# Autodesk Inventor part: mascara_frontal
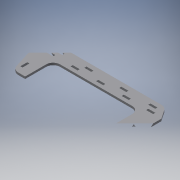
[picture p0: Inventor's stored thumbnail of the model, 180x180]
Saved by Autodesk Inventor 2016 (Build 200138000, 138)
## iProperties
Created: 2017-06
Part Number: mascara_frontal
Material: Generic
Document SubType Name: Modeling
Designer: laboratorioesan
Density: 1 g/cm^3
Appearance: Default
Author: laboratorioesan
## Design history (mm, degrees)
sketch "Sketch1"
  geometry: L1 (280, 0)-(340, 0) reference; L2 (340, 0)-(340, 18.5) reference; L3 (280, 18.5)-(340, 18.5) reference; L4 (280, 0)-(280, 18.5) reference; L5 (70, 0)-(130, 0) reference; L6 (130, 0)-(130, 18.5) reference; L7 (70, 18.5)-(130, 18.5) reference; L8 (70, 0)-(70, 18.5) reference; L9 (500, 0)-(560, 0) reference; L10 (560, 0)-(560, 18.5) reference; L11 (500, 18.5)-(560, 18.5) reference; L12 (500, 0)-(500, 18.5) reference; L13 (720, 0)-(780, 0) reference; L14 (780, 0)-(780, 18.5) reference; L15 (720, 18.5)-(780, 18.5) reference; L16 (720, 0)-(720, 18.5) reference; L17 (930, 0)-(990, 0) reference; L18 (990, 0)-(990, 18.5) reference; L19 (930, 18.5)-(990, 18.5) reference; L20 (930, 0)-(930, 18.5) reference; L21 (0, 0)-(0, 18.5) reference; L22 (130, -432.5)-(130, 0) reference; L23 (111.5, -432.5)-(111.5, 0) reference; L24 (930, -432.5)-(930, 0) reference; L25 (948.5, -432.5)-(948.5, 0) reference; L26 (1060, 0)-(1060, 18.5) reference; L27 (990, 104.496)-(70, 104.496); L28 (70, 104.496)-(0, 0); L29 (0, 0)-(0, -84.685); L30 (57, -270.723)-(130, -270.723); L31 (1060, 0)-(990, 104.496); L32 (130, -270.723)-(160, -270.723); L33 (160, -270.723)-(160, -30); L34 (160, -30)-(900, -30); L35 (900, -30)-(900, -270.723); L36 (900, -270.723)-(1003, -270.723); L37 (1003, -270.723)-(1060, -84.685); L38 (1060, -84.685)-(1060, 0); L39 (0, -84.685)-(57, -270.723)
  constraints: 26 end point, 4 perpendicular, 3 point on line, 2 horizontal, 2 horizontal alignment, 2 vertical, 2 vertical alignment
  dimensions: "d0" = 30 distance of L30.end L32.end; "d1" = 30 distance between parallel lines of L24 L35; "d2" = 30 horizontal distance of L17.start L34.end; "d3" = 70 distance between parallel lines of L29 L8; "d4" = 70 distance between parallel lines of L38 L18 (derived); "d6" = 103 distance of L35.end L36.end; "d7" = 103 distance of L30.start L32.end
extrude "Extrusion1" new body sketch "Sketch1" distance "d8" = 18.5; taper "d9" = 0 deg
fillet "Fillet1" dims "d10" = 60
fillet "Fillet2" dims "d11" = 60
sketch "Sketch2"
  geometry: L1 (930, 0)-(930, 18.5) reference; L2 (930, 18.5)-(990, 18.5) reference; L3 (990, 18.5)-(990, 0) reference; L4 (990, 0)-(930, 0) reference; L5 (720, 0)-(720, 18.5) reference; L6 (720, 18.5)-(780, 18.5) reference; L7 (780, 18.5)-(780, 0) reference; L8 (780, 0)-(720, 0) reference; L9 (500, 0)-(500, 18.5) reference; L10 (500, 18.5)-(560, 18.5) reference; L11 (560, 18.5)-(560, 0) reference; L12 (560, 0)-(500, 0) reference; L13 (70, 0)-(70, 18.5) reference; L14 (70, 18.5)-(130, 18.5) reference; L15 (130, 18.5)-(130, 0) reference; L16 (130, 0)-(70, 0) reference; L17 (280, 0)-(280, 18.5) reference; L18 (280, 18.5)-(340, 18.5) reference; L19 (340, 18.5)-(340, 0) reference; L20 (340, 0)-(280, 0) reference; L21 (52.176, 77.889)-(0, 0) reference; L22 (0, 0)-(0, -84.685) reference; L23 (0, -84.685)-(44.002, -228.3) reference; L24 (101.37, -270.723)-(160, -270.723) reference; L25 (160, -270.723)-(160, -90) reference; L26 (220, -30)-(840, -30) reference; L27 (900, -90)-(900, -270.723) reference; L28 (900, -270.723)-(958.63, -270.723) reference; L29 (1015.998, -228.3)-(1060, -84.685) reference; L30 (1060, -84.685)-(1060, 0) reference; L31 (1060, 0)-(1007.824, 77.889) reference; L32 (957.975, 104.496)-(102.025, 104.496) reference; L33 (960, 67)-(900, 67); L34 (900, 67)-(900, 48.5); L35 (900, 48.5)-(960, 48.5); L36 (960, 48.5)-(960, 67); L37 (710, 48.5)-(650, 48.5); L38 (650, 48.5)-(650, 67); L39 (650, 67)-(710, 67); L40 (710, 67)-(710, 48.5); L41 (410, 48.5)-(350, 48.5); L42 (350, 48.5)-(350, 67); L43 (350, 67)-(410, 67); L44 (410, 67)-(410, 48.5); L45 (160, 48.5)-(100, 48.5); L46 (100, 48.5)-(100, 67); L47 (100, 67)-(160, 67); L48 (160, 67)-(160, 48.5); L49 (948.5, -432.5)-(948.5, 0) reference; L50 (997, -100)-(978.5, -100); L51 (978.5, -100)-(978.5, -40); L52 (978.5, -40)-(997, -40); L53 (997, -40)-(997, -100); L54 (997, -155)-(978.5, -155); L55 (978.5, -155)-(978.5, -215); L56 (978.5, -215)-(997, -215); L57 (997, -215)-(997, -155); L58 (111.5, -432.5)-(111.5, 0) reference; L59 (81.5, -100)-(63, -100); L60 (63, -100)-(63, -40); L61 (63, -40)-(81.5, -40); L62 (81.5, -40)-(81.5, -100); L63 (81.5, -155)-(63, -155); L64 (63, -155)-(63, -215)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; A1 r 60 centre (102.025, 44.496) between (102.025, 104.496) and (52.176, 77.889) reference; A2 r 60 centre (101.37, -210.723) between (44.002, -228.3) and (101.37, -270.723) reference; A3 r 60 centre (220, -90) between (220, -30) and (160, -90) reference; A4 r 60 centre (840, -90) between (900, -90) and (840, -30) reference; A5 r 60 centre (958.63, -210.723) between (958.63, -270.723) and (1015.998, -228.3) reference; A6 r 60 centre (957.975, 44.496) between (1007.824, 77.889) and (957.975, 104.496) reference; 6 further points
  constraints: 64 end point, 16 parallel, 8 horizontal, 8 perpendicular, 7 horizontal alignment, 5 midpoint, 5 point on line, 4 vertical alignment
  dimensions: "d12" = 60 distance of L35.end L34.end; "d13" = 18.5 distance of L34.end L33.end; "d14" = 60 distance of L38.end L39.end; "d15" = 60 distance of L42.end L43.end; "d16" = 60 distance of L46.end L47.end; "d17" = 30 distance from line of L1.end L35; "d18" = 190 distance of L47.end L42.end; "d19" = 190 distance of L37.start L34.end; "d20" = 18.5 distance of L51.end L52.end; "d21" = 60 distance of L50.end L51.end; "d22" = 40 vertical distance of L3.end L52.end; "d23" = 60 distance of L55.end L54.end; "d24" = 30 distance between parallel lines of L49 L51; "d25" = 18.5 distance of L60.end L61.end; "d26" = 60 distance of L64.end L63.end; "d27" = 55 distance of L50.end L54.end; "d28" = 30 distance from line of L58 L59.start
extrude "Extrusion2" cut sketch "Sketch2" distance "d29" = 18.5; taper "d30" = 0 deg
sketch "Sketch3"
  geometry: L1 (81.5, -40)-(81.5, -100) reference; L2 (81.5, -100)-(63, -100) reference; L3 (63, -100)-(63, -40) reference; L4 (63, -40)-(81.5, -40) reference; L5 (997, -40)-(997, -100) reference; L6 (997, -100)-(978.5, -100) reference; L7 (978.5, -100)-(978.5, -40) reference; L8 (978.5, -40)-(997, -40) reference; L9 (410, 67)-(410, 48.5) reference; L10 (410, 48.5)-(350, 48.5) reference; L11 (350, 48.5)-(350, 67) reference; L12 (350, 67)-(410, 67) reference; L13 (900, 48.5)-(900, 67) reference; L14 (900, 67)-(960, 67) reference; L15 (960, 67)-(960, 48.5) reference; L16 (960, 48.5)-(900, 48.5) reference; L17 (710, 67)-(710, 48.5) reference; L18 (710, 48.5)-(650, 48.5) reference; L19 (650, 48.5)-(650, 67) reference; L20 (650, 67)-(710, 67) reference; L21 (160, 67)-(160, 48.5) reference; L22 (160, 48.5)-(100, 48.5) reference; L23 (100, 48.5)-(100, 67) reference; L24 (100, 67)-(160, 67) reference; L25 (978.5, -215)-(978.5, -155) reference; L26 (978.5, -155)-(997, -155) reference; L27 (997, -155)-(997, -215) reference; L28 (997, -215)-(978.5, -215) reference; L29 (63, -215)-(63, -155) reference; L30 (63, -155)-(81.5, -155) reference; L31 (81.5, -155)-(81.5, -215) reference; L32 (81.5, -215)-(63, -215) reference; L33 (930, 0)-(930, 18.5) reference; L34 (930, 18.5)-(990, 18.5) reference; L35 (990, 18.5)-(990, 0) reference; L36 (990, 0)-(930, 0) reference; L37 (720, 0)-(720, 18.5) reference; L38 (720, 18.5)-(780, 18.5) reference; L39 (780, 18.5)-(780, 0) reference; L40 (780, 0)-(720, 0) reference; L41 (500, 0)-(500, 18.5) reference; L42 (500, 18.5)-(560, 18.5) reference; L43 (560, 18.5)-(560, 0) reference; L44 (560, 0)-(500, 0) reference; L45 (70, 0)-(70, 18.5) reference; L46 (70, 18.5)-(130, 18.5) reference; L47 (130, 18.5)-(130, 0) reference; L48 (130, 0)-(70, 0) reference; L49 (280, 0)-(280, 18.5) reference; L50 (280, 18.5)-(340, 18.5) reference; L51 (340, 18.5)-(340, 0) reference; L52 (340, 0)-(280, 0) reference; L53 (52.176, 77.889)-(0, 0) reference; L54 (0, 0)-(0, -84.685) reference; L55 (0, -84.685)-(44.002, -228.3) reference; L56 (101.37, -270.723)-(160, -270.723) reference; L57 (160, -270.723)-(160, -90) reference; L58 (220, -30)-(840, -30) reference; L59 (900, -90)-(900, -270.723) reference; L60 (900, -270.723)-(958.63, -270.723) reference; L61 (1015.998, -228.3)-(1060, -84.685) reference; L62 (1060, -84.685)-(1060, 0) reference; L63 (1060, 0)-(1007.824, 77.889) reference; L64 (957.975, 104.496)-(102.025, 104.496) reference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; A1 r 60 centre (102.025, 44.496) between (102.025, 104.496) and (52.176, 77.889) reference; A2 r 60 centre (101.37, -210.723) between (44.002, -228.3) and (101.37, -270.723) reference; A3 r 60 centre (220, -90) between (220, -30) and (160, -90) reference; A4 r 60 centre (840, -90) between (900, -90) and (840, -30) reference; A5 r 60 centre (958.63, -210.723) between (958.63, -270.723) and (1015.998, -228.3) reference; A6 r 60 centre (957.975, 44.496) between (1007.824, 77.889) and (957.975, 104.496) reference; 1 further point
  constraints: 16 end point, 4 parallel, 2 horizontal, 2 perpendicular
extrude "Extrusion3" join sketch "Sketch3" distance "d31" = 18.5; taper "d32" = 0 deg
sketch "Sketch4"
  geometry: L1 (410, 67)-(410, 48.5) reference; L2 (410, 48.5)-(350, 48.5) reference; L3 (350, 48.5)-(350, 67) reference; L4 (350, 67)-(410, 67) reference; L5 (900, 48.5)-(900, 67) reference; L6 (900, 67)-(960, 67) reference; L7 (960, 67)-(960, 48.5) reference; L8 (960, 48.5)-(900, 48.5) reference; L9 (710, 67)-(710, 48.5) reference; L10 (710, 48.5)-(650, 48.5) reference; L11 (650, 48.5)-(650, 67) reference; L12 (650, 67)-(710, 67) reference; L13 (160, 67)-(160, 48.5) reference; L14 (160, 48.5)-(100, 48.5) reference; L15 (100, 48.5)-(100, 67) reference; L16 (100, 67)-(160, 67) reference; L17 (978.5, -215)-(978.5, -155) reference; L18 (978.5, -155)-(997, -155) reference; L19 (997, -155)-(997, -215) reference; L20 (997, -215)-(978.5, -215) reference; L21 (63, -215)-(63, -155) reference; L22 (63, -155)-(81.5, -155) reference; L23 (81.5, -155)-(81.5, -215) reference; L24 (81.5, -215)-(63, -215) reference; L25 (930, 0)-(930, 18.5) reference; L26 (930, 18.5)-(990, 18.5) reference; L27 (990, 18.5)-(990, 0) reference; L28 (990, 0)-(930, 0) reference; L29 (720, 0)-(720, 18.5) reference; L30 (720, 18.5)-(780, 18.5) reference; L31 (780, 18.5)-(780, 0) reference; L32 (780, 0)-(720, 0) reference; L33 (500, 0)-(500, 18.5) reference; L34 (500, 18.5)-(560, 18.5) reference; L35 (560, 18.5)-(560, 0) reference; L36 (560, 0)-(500, 0) reference; L37 (70, 0)-(70, 18.5) reference; L38 (70, 18.5)-(130, 18.5) reference; L39 (130, 18.5)-(130, 0) reference; L40 (130, 0)-(70, 0) reference; L41 (280, 0)-(280, 18.5) reference; L42 (280, 18.5)-(340, 18.5) reference; L43 (340, 18.5)-(340, 0) reference; L44 (340, 0)-(280, 0) reference; L45 (52.176, 77.889)-(0, 0) reference; L46 (0, 0)-(0, -84.685) reference; L47 (0, -84.685)-(44.002, -228.3) reference; L48 (101.37, -270.723)-(160, -270.723) reference; L49 (160, -270.723)-(160, -90) reference; L50 (220, -30)-(840, -30) reference; L51 (900, -90)-(900, -270.723) reference; L52 (900, -270.723)-(958.63, -270.723) reference; L53 (1015.998, -228.3)-(1060, -84.685) reference; L54 (1060, -84.685)-(1060, 0) reference; L55 (1060, 0)-(1007.824, 77.889) reference; L56 (957.975, 104.496)-(102.025, 104.496) reference; L57 (530, -30)-(530, -112.619); C1 r 5.25 at (60, -40); C2 r 5.25 at (1000, -40); A1 r 60 centre (102.025, 44.496) between (102.025, 104.496) and (52.176, 77.889) reference; A2 r 60 centre (101.37, -210.723) between (44.002, -228.3) and (101.37, -270.723) reference; A3 r 60 centre (220, -90) between (220, -30) and (160, -90) reference; A4 r 60 centre (840, -90) between (900, -90) and (840, -30) reference; A5 r 60 centre (958.63, -210.723) between (958.63, -270.723) and (1015.998, -228.3) reference; A6 r 60 centre (957.975, 44.496) between (1007.824, 77.889) and (957.975, 104.496) reference; 1 further point
  constraints: 2 centre point, 2 end point, 1 midpoint, 1 symmetric about line, 1 vertical, 1 other
  dimensions: "d33" = 10.5 diameter of C1; "d34" = 40 vertical distance of L37.start C1.centre; "d35" = 10 horizontal distance of L37.start C1.centre
extrude "Extrusion4" cut sketch "Sketch4" distance "d36" = 18.5; taper "d37" = 0 deg
body "Solid1"
node "Reference1"
node "Reference2"
node "Reference3"
node "Reference4"
node "Reference5"
node "Reference6"
node "Reference7"
node "Reference8"
node "Reference9"
node "Reference10"
node "Reference11"
node "Projected Loop1"
node "Reference12"
node "Reference13"
node "Projected Loop2"
node "Projected Loop3"
